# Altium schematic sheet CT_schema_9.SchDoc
size 278 x 170 mm
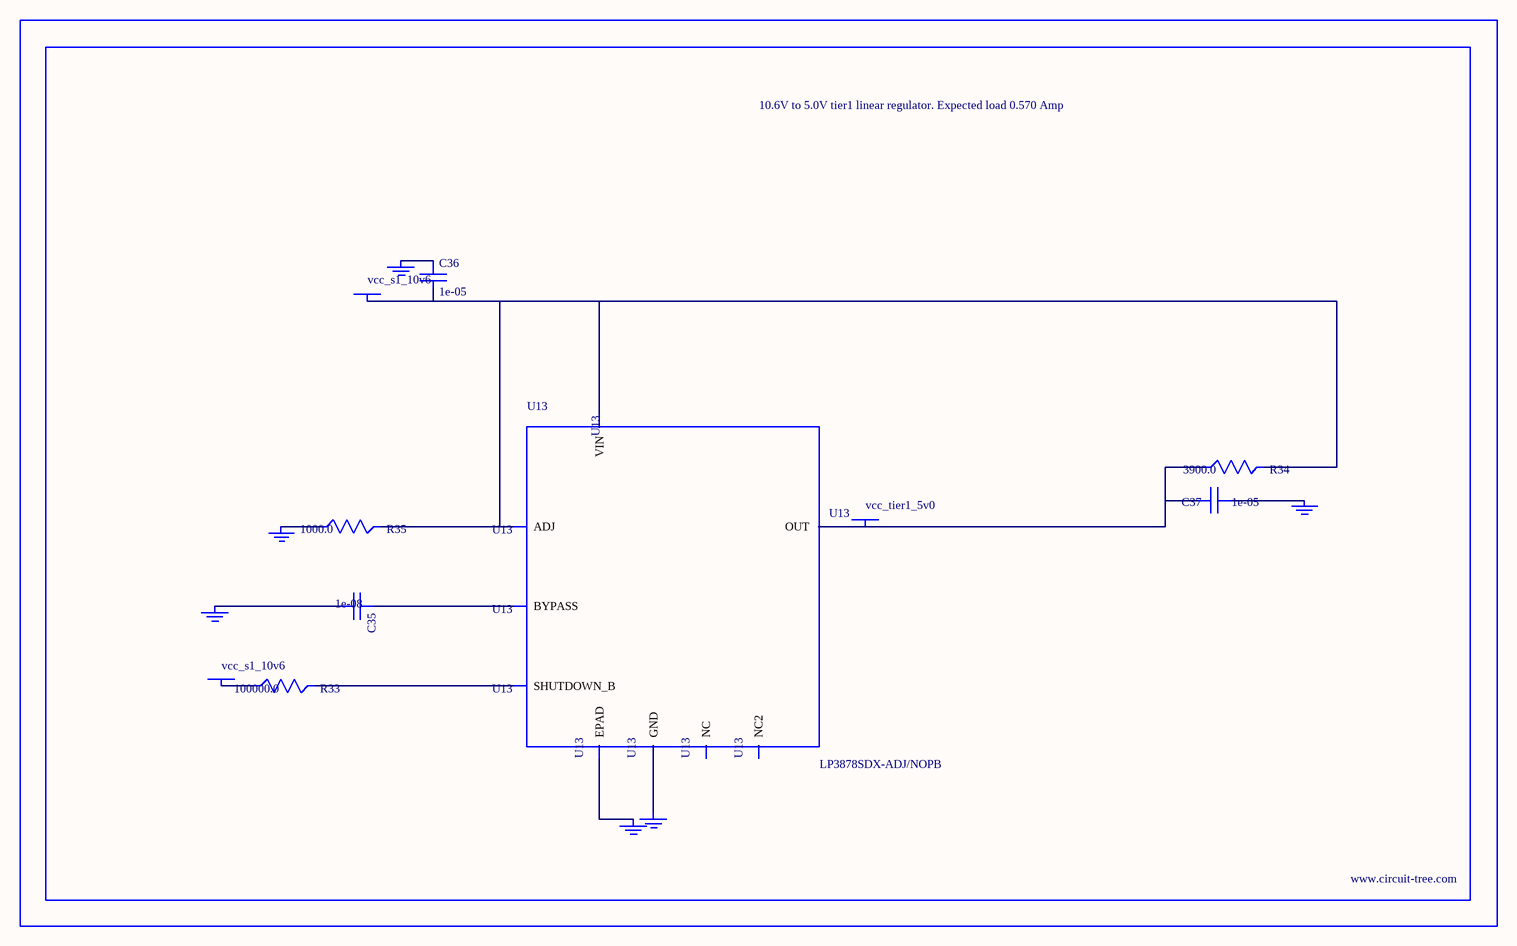
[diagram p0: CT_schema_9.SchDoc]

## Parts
BORDER8  (no value)
C35  1e-08  [C0402]
C36  1e-05  [C1206]
C37  1e-05  [C1210]
GND_INSTANCE_8_0  (no value)
GND_INSTANCE_8_1  (no value)
GND_INSTANCE_8_2  (no value)
GND_INSTANCE_8_3  (no value)
GND_INSTANCE_8_4  (no value)
GND_INSTANCE_8_5  (no value)
POWER_INSTANCE_8_0  vcc_s1_10v6
POWER_INSTANCE_8_1  vcc_s1_10v6
POWER_INSTANCE_8_2  vcc_tier1_5v0
R33  100000.0  [R0603]
R34  3900.0  [R0603]
R35  1000.0  [R0603]
U13  LP3878SDX-ADJ/NOPB  [WSON-8]

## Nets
NetC35_1: C35.1 U13.1(BYPASS)
NetC35_2: C35.2 GND_INSTANCE_8_0.0(GND)
NetC36_1: C36.1 GND_INSTANCE_8_1.0(GND)
NetC36_2: C36.2 POWER_INSTANCE_8_0.0(PWR) R34.2 R35.2 U13.4(VIN) U13.6(ADJ)
NetC37_1: C37.1 GND_INSTANCE_8_2.0(GND)
NetC37_2: C37.2 POWER_INSTANCE_8_2.0(PWR) R34.1 U13.5(OUT)
NetGND_INSTANCE_8_3_0: GND_INSTANCE_8_3.0(GND) R35.1
NetGND_INSTANCE_8_4_0: GND_INSTANCE_8_4.0(GND) U13.PAD(EPAD)
NetGND_INSTANCE_8_5_0: GND_INSTANCE_8_5.0(GND) U13.3(GND)
NetPOWER_INSTANCE_8_1_0: POWER_INSTANCE_8_1.0(PWR) R33.1
NetR33_2: R33.2 U13.8(SHUTDOWN_B)

Not connected (* = marked no-connect by the designer): U13 2(NC) 7(NC2)

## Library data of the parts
BORDER8 = BORDER_PAGE8
C35 = C0402C103K3RAC
C36 = C1206C106K3RACTU
C37 = GRM32DR61E106MA12L
GND_INSTANCE_8_0-GND_INSTANCE_8_5 = GND
POWER_INSTANCE_8_0-POWER_INSTANCE_8_2 = PWR
R33 = RC0603JR-07100KL
R34 = RC0603JR-073K9L
R35 = RC0603JR-071KL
